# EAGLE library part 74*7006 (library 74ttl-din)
NOR/NAND/INVERTER
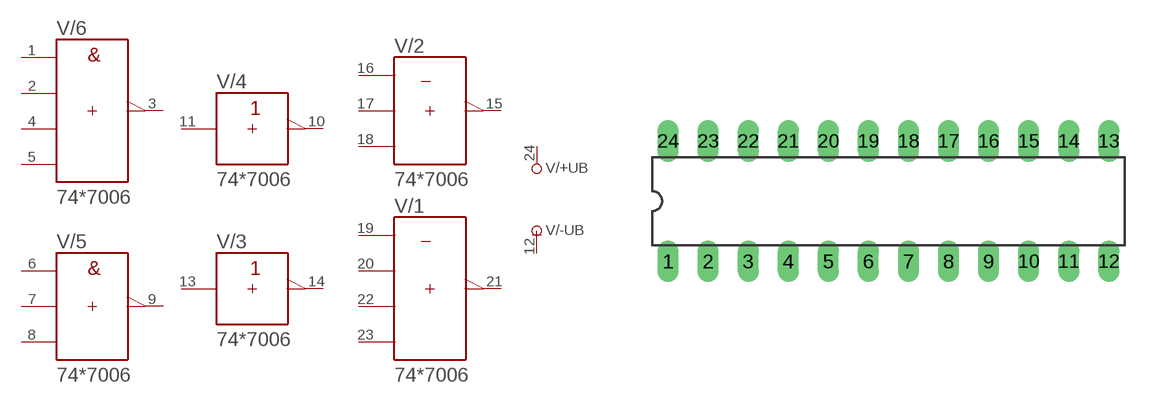
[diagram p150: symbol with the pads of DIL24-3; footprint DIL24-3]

Designator prefix V; gates /+UB=+UB /-UB=-UB /1=7006_6 /2=7006_5 /3=7006_4 /4=7006_3 /5=7006_2 /6=7006_1

## 747006N  [DIL24-3]
1  /6:A  in
2  /6:B  in
3  /6:Y  out
4  /6:C  in
5  /6:D  in
6  /5:A  in
7  /5:B  in
8  /5:C  in
9  /5:Y  out
10  /4:Y  out
11  /4:A  in
12  /-UB:-UB  pwr
13  /3:A  in
14  /3:Y  out
15  /2:Y  out
16  /2:A  in
17  /2:B  in
18  /2:C  in
19  /1:A  in
20  /1:B  in
21  /1:Y  out
22  /1:C  in
23  /1:D  in
24  /+UB:+UB  pwr

## Footprint DIL24-3 (pad centres in mm)
Dual In Line Package 0.3 inch
drill 0.813 long: 1 -13.97,-3.81; 2 -11.43,-3.81; 3 -8.89,-3.81; 4 -6.35,-3.81; 5 -3.81,-3.81; 6 -1.27,-3.81; 7 1.27,-3.81; 8 3.81,-3.81; 9 6.35,-3.81; 10 8.89,-3.81; 11 11.43,-3.81; 12 13.97,-3.81; 13 13.97,3.81; 14 11.43,3.81; 15 8.89,3.81; 16 6.35,3.81; 17 3.81,3.81; 18 1.27,3.81; 19 -1.27,3.81; 20 -3.81,3.81; 21 -6.35,3.81; 22 -8.89,3.81; 23 -11.43,3.81; 24 -13.97,3.81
